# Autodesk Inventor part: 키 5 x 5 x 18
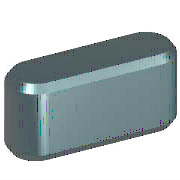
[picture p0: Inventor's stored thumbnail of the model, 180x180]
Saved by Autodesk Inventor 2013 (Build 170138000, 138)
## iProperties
Created: 2012-02
Part Number: 키 5 x 5 x 18
Material: 강철, 연강
Description: 키 및 해당 키홈
Document SubType Name: Modeling
Standard: KS B 1311
Designer: mduedu
Standards Organization: KS
Language: ko-KR
Size Designation: 5 x 5 x 18
Categories: <MemberInstance><Categories><Category DisplayName="샤프트 부품" InternalName="7f7aeb1f-a693-4053-b835-cee3144e0d98" Mnemonic="SHFT"><Category DisplayName="키" Interna
Density: 7.86 g/cm^3
Mass: 3.27476 g
Surface Area: 3.57848 cm^2
Volume: 0.416636 cm^3
IsCustomPart: 1
Author: mduedu
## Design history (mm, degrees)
workplane "Work Plane1"
workplane "Work Plane2"
sketch "스케치1"
  geometry: L1 (2.5, 2.5)-(15.5, 2.5); L2 (15.5, -2.5)-(2.5, -2.5); L3 (0, 9.4)-(0, -7.4) reference; L4 (-5, 0)-(30, 0) reference; L5 (18, 0)-(18, 7); A1 r 2.5 centre (2.5, 0) between (2.5, 2.5) and (2.5, -2.5); A2 r 2.5 centre (15.5, 0) between (15.5, -2.5) and (15.5, 2.5)
  constraints: 6 end point, 5 point on circle, 4 tangent, 3 point on line, 2 centre point, 1 horizontal, 1 parallel, 1 perpendicular
  dimensions: "d0" = 2.5 radius of A1 (= 0.5 x PB); "d13" = 2.5 radius of A2 (= 0.5 x PB); "d14" = 18 distance between parallel lines of L5 L3 (= NLG)
extrude "본체1" new body sketch "스케치1" taper "d3" = 0 deg; stored distance "d4" = 10
workplane "Work Plane3"
body "Solid1"
chamfer "모따기1" distance "d8" = 0.4 (= PHH); stored, may be unused: second distance "d9" = 0.4 (= PHH), angle "d15" = 45 deg
other parameters: "d1" = -3 (= -PNT), "d2" = 2 (= PH - PNT), "NLG" = 18 [user parameter; used in 3 equation terms], "PB" = 5 [user parameter; used in 2 equation terms], "PNT" = 3 [user parameter; used in 2 equation terms], "PH" = 5 [user parameter; used in 1 equation term], "PHH" = 0.4 [user parameter; used in 2 equation terms], "d10" = 0, "d16" = 0, "d17" = 0, "d18" = 0, "WDMIN" = 12 [user parameter], "PLB2" = 18 (= NLG) [user parameter], "WDMAX" = 17 [user parameter], "PLB1" = 18 (= NLG) [user parameter], "RR" = 0.16 [user parameter], "PUEB" = 2.3 [user parameter]
